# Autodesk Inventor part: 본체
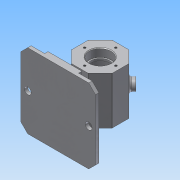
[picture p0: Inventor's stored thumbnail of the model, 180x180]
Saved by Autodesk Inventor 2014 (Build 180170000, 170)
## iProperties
Created: 2018-06
Part Number: 본체
Material: 알루미늄 6061
Document SubType Name: Modeling
Designer: SEO-12
Mass: 554.041 g
Surface Area: 601.935 cm^2
Volume: 204.443 cm^3
Density: 2.71 g/cm^3
Appearance: 알루미늄 - 평지
Author: SEO-12
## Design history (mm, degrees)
sketch "스케치2" dims "d1" = 60
  geometry: L1 (12.426, 30)-(30, 12.426); L2 (30, 12.426)-(30, -12.426); L3 (30, -12.426)-(12.426, -30); L4 (12.426, -30)-(-12.426, -30); L5 (-12.426, -30)-(-30, -12.426); L6 (-30, -12.426)-(-30, 12.426); L7 (-30, 12.426)-(-12.426, 30); L8 (-12.426, 30)-(12.426, 30); 4 further points
  constraints: 16 end point, 2 coincident, 1 horizontal, 1 midpoint, 1 vertical alignment, 19 other
extrude "돌출1" new body sketch "스케치2" stored distance "d2" = 70; taper "d3" = 0 deg
sketch "스케치3"
  geometry: L1 (30, -35)-(-30, -35) reference; L2 (-30, -35)-(-30, 35) reference; L3 (-30, 35)-(30, 35) reference; L4 (30, 35)-(30, -35) reference; L5 (0, 35)-(0, -35); L6 (0, 35)-(16, 35); L7 (16, 23)-(16, 35); L8 (16, 23)-(14, 23); L9 (14, 23)-(14, 20); L10 (14, 20)-(25, 20); L11 (25, 20)-(25, -20); L12 (25, -20)-(14, -20); L13 (14, -20)-(14, -23); L14 (14, -23)-(16, -23); L15 (16, -23)-(16, -35); L16 (16, -35)-(0, -35); 1 further point
  constraints: 24 end point, 5 parallel, 3 perpendicular, 2 collinear, 2 midpoint, 2 point on line
  dimensions: "d4" = 12 distance between parallel lines of L8 L6; "d5" = 3 distance between parallel lines of L10 L8; "d6" = 40 distance between parallel lines of L12 L10; "d7" = 3 distance between parallel lines of L14 L12; "d8" = 32 diameter of L7 L5; "d9" = 28 diameter of L9 L5; "d10" = 50 diameter of L11 L5; "d11" = 28 diameter of L13 L5; "d12" = 32 diameter of L15 L5
revolve "회전1" sketch "스케치3" stored, may be unused: angle "d13" = 90 deg
node "작업 평면1"
sketch "스케치4"
  geometry: L1 (55, 55)-(-55, 55); L2 (-55, 55)-(-55, -55); L3 (-55, -55)-(55, -55); L4 (55, -55)-(55, 55); L5 (55, 55)-(-55, -55); L6 (-55, 55)-(55, -55); 1 further point
  constraints: 12 end point, 2 midpoint, 2 parallel, 1 horizontal, 1 perpendicular
  dimensions: "d15" = 110 distance of L3.end L2.end; "d16" = 110 distance of L2.end L1.end
extrude "돌출2" join sketch "스케치4" distance "d17" = 5; taper "d18" = 0 deg
sketch "스케치5"
  geometry: L1 (25, -55)-(-25, -55); L2 (-25, -55)-(-25, 55); L3 (-25, 55)-(25, 55); L4 (25, 55)-(25, -55); L5 (25, -55)-(-25, 55); L6 (-25, -55)-(25, 55); 1 further point
  constraints: 12 end point, 2 midpoint, 2 parallel, 1 horizontal, 1 perpendicular
  dimensions: "d19" = 50 distance of L2.end L3.end; "d20" = 110 distance of L1.end L2.end
extrude "돌출3" join sketch "스케치5" distance "d21" = 5; taper "d22" = 0 deg
sketch "스케치6"
  geometry: L1 (25, -55)-(25, 55) reference; L2 (0, -19)-(0, 19); L3 (5, -19)-(5, 19); L4 (-5, 19)-(-5, -19); A1 r 5 centre (0, -19) between (-5, -19) and (5, -19); A2 r 5 centre (0, 19) between (5, 19) and (-5, 19); 2 further points
  constraints: 8 end point, 4 point on circle, 4 tangent, 2 centre point, 2 parallel, 1 coincident, 1 midpoint
  dimensions: "d23" = 38 distance of L2.end L2.start; "d25" = 5 radius of A1
extrude "돌출4" join sketch "스케치6" stored distance "d26" = 5; taper "d27" = 0 deg
sketch "스케치7"
  geometry: L1 (55, -55)-(55, 55) reference; C1 r 5 at (45, 0); 1 further point
  constraints: 1 centre point, 1 horizontal alignment
  dimensions: "d28" = 10 diameter of C1; "d29" = 10 distance from line of L1 C1.centre
extrude "돌출5" cut sketch "스케치7" stored distance "d30" = 0; taper "d31" = 0 deg
chamfer "모따기1" distance "d32" = 10; stored, may be unused: second distance "d33" = 2, angle "d34" = 45 deg
sketch "스케치8"
  geometry: L1 (-55, -62)-(-55, -57) reference; L2 (-55, -57)-(-50, -57) reference; L3 (-50, -57)-(-50, -62) reference; L4 (-50, -62)-(-55, -62) reference; L5 (55, -57)-(55, -62) reference; L6 (55, -62)-(50, -62) reference; L7 (50, -62)-(50, -57) reference; L8 (50, -57)-(55, -57) reference; L9 (-12.426, 30)-(12.426, 30) reference; L10 (12.426, 30)-(30, 12.426) reference; L11 (30, 12.426)-(30, -12.426) reference; L12 (30, -12.426)-(12.426, -30) reference; L13 (12.426, -30)-(5, -30) reference; L14 (5, -30)-(5, -52) reference; L15 (5, -52)-(25, -52) reference; L16 (25, -52)-(25, -57) reference; L17 (25, -57)-(40, -57) reference; L18 (40, -57)-(40, -62) reference; L19 (40, -62)-(-40, -62) reference; L20 (-40, -62)-(-40, -57) reference; L21 (-40, -57)-(-25, -57) reference; L22 (-25, -57)-(-25, -52) reference; L23 (-25, -52)-(-5, -52) reference; L24 (-5, -52)-(-5, -30) reference; L25 (-5, -30)-(-12.426, -30) reference; L26 (-12.426, -30)-(-30, -12.426) reference; L27 (-30, -12.426)-(-30, 12.426) reference; L28 (-30, 12.426)-(-12.426, 30) reference; L29 (0, 0)-(26.163, 26.163); C1 r 25 at (0, 0) reference; 1 further point
  constraints: 2 end point, 1 parallel
  dimensions: "d35" = 37 distance of L29.start L29.end
  node "절단 모서리 투영2"
node "작업 평면2"
sketch "스케치9"
  geometry: C1 r 8 at (0, 0); 1 further point
  constraints: 1 centre point, 1 coincident
  dimensions: "d36" = 16 diameter of C1
extrude "돌출6" join sketch "스케치9" stored distance "d37" = 5; taper "d38" = 0 deg
sketch "스케치10"
  geometry: C1 r 8 at (0, 0) reference; 1 further point
  constraints: 1 coincident
hole "구멍1" sketch "스케치10" at (0, 0) diameter "d39" = 8; stored, may be unused: countersink angle "d43" = 90 deg, drill point angle "d45" = 0 deg; dims "d40" = 6, "d41" = 4, "d42" = 2, "d44" = 8
sketch "스케치11"
  geometry: L1 (24.853, 0)-(0, 0) reference; L2 (-17.574, 0)-(-17.574, 70) reference; 2 further points
  constraints: 1 other
  dimensions: "d46" = 35 distance from line of point (12.426, 35) L1; "d47" = 30 distance from line of point (12.426, 35) L2
feature "엠보싱1" sketch "스케치11" dims "d4" = 12, "d5" = 3, "d6" = 40, "d7" = 3, "d8" = 32, "d9" = 28, "d10" = 50, "d11" = 28, "d12" = 32, "d48" = 0.5, "d49" = 0
fillet "모깎기1" dims "d50" = 1
fillet "모깎기2" dims "d51" = 2
chamfer "모따기2" distance "d52" = 1; stored, may be unused: second distance "d53" = 2, angle "d54" = 45 deg
fillet "모깎기3" dims "d55" = 3
chamfer "모따기3" distance "d56" = 1; stored, may be unused: second distance "d57" = 2, angle "d58" = 45 deg
fillet "모깎기4" dims "d59" = 3
fillet "모깎기5" dims "d60" = 0.3
sketch "스케치12"
  geometry: L1 (-30, 12.012)-(-30, -12.012) reference; L2 (0, 0)-(23, 0); C1 r 17 at (0, 0) reference; 1 further point
  constraints: 2 end point, 1 coincident, 1 perpendicular
  dimensions: "d61" = 23 distance of L2.start L2.end
hole "구멍2" sketch "스케치12" at (23, 0) diameter "d62" = 3.242; stored, may be unused: countersink angle "d66" = 82 deg, drill point angle "d68" = 118 deg; dims "d63" = 8, "d64" = 3.023, "d65" = 2, "d67" = 10
node "솔리드1"
mirror "대칭1"
pattern_circular "원형 패턴1" dims angle "d70" = 360 deg
mirror "대칭2"
node "절단 모서리 투영1"
other parameters: "d14" = -62
